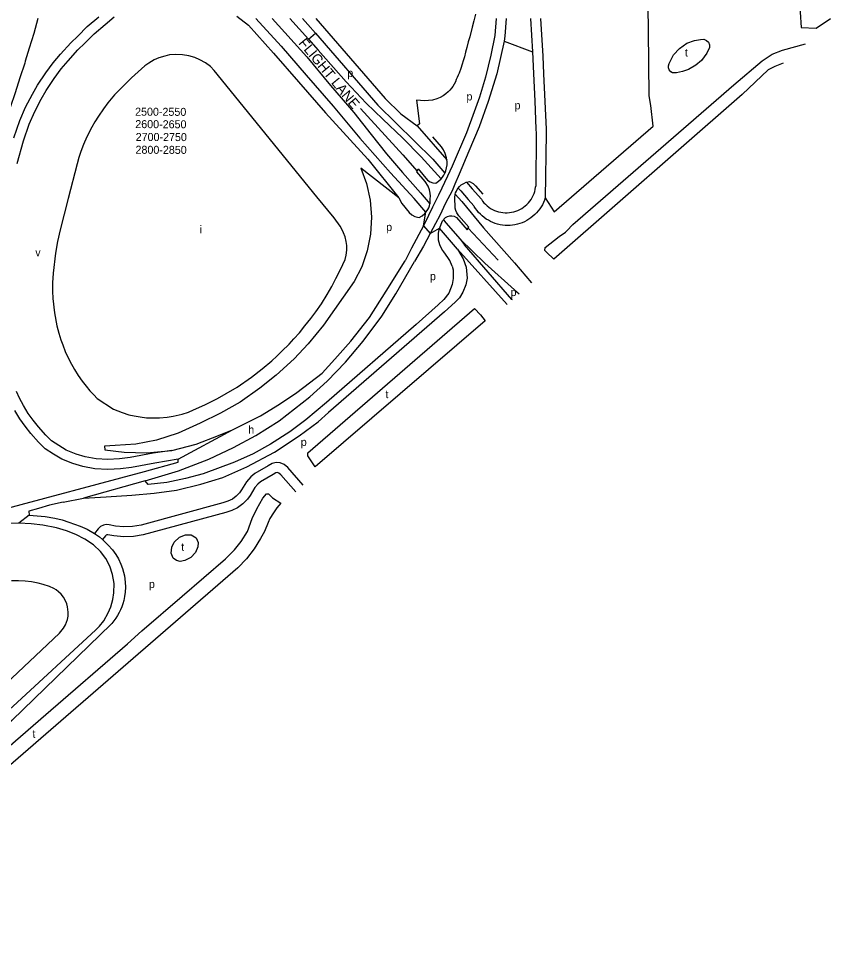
# Model space of a CAD drawing. Extents: x 154765 to 156627, y 383996 to 386132.
# Drawn here: x 155986.3 to 156392.2, y 384040.6 to 384500 of the extents above; entities that cross this region are included whole.
import ezdxf

# ---------------------------------------------------------------- set-up
doc = ezdxf.new("R2010")
doc.units = 0
for name, color, linetype in [('BLT_Basislijn', 7, 'Continuous'), ('BLT_Bebouwing', 7, 'Continuous'), ('BLT_Centroide', 7, 'Continuous'), ('BLT_Huisnummer_reeks', 7, 'Continuous'), ('BLT_Straatnaam', 7, 'Continuous'), ('BLT_Vlakafsluiter', 7, 'Continuous')]:
    doc.layers.add(name, color=color, linetype=linetype)

msp = doc.modelspace()

# ---------------------------------------------------------------- linework, layer by layer
at = {"layer": 'BLT_Basislijn'}
for p, q in [((156095.52, 384501.07), (156101.2, 384496.63)), ((156121.91, 384499.98), (156131.18, 384489.58)), ((156128.33, 384499.98), (156130.93, 384496.97)), ((156130.93, 384496.97), (156134.7, 384492.61)), ((156134.93, 384499.98), (156169.64, 384459.92)), ((156131.18, 384489.58), (156134.7, 384492.61)), ((156134.7, 384492.61), (156165.86, 384456.65)), ((156224.31, 384491.47), (156222.3, 384481.68)), ((156131.18, 384489.58), (156136.02, 384484.16)), ((156229.05, 384488.58), (156225.43, 384472.27)), ((156113.81, 384482.67), (156126.3, 384468.25)), ((156117.52, 384486.02), (156130.06, 384471.54)), ((156136.02, 384484.16), (156150.01, 384468.24)), ((156130.41, 384480.75), (156142.29, 384466.38)), ((156222.3, 384481.68), (156219.64, 384470.58)), ((156130.06, 384471.54), (156143.57, 384456.1)), ((156219.64, 384470.58), (156216.75, 384460.69)), ((156225.43, 384472.27), (156221.09, 384458.51)), ((156126.3, 384468.25), (156139.8, 384452.81)), ((156142.29, 384466.38), (156153.87, 384452.87)), ((156150.01, 384468.24), (156160.14, 384457.62)), ((156169.64, 384459.92), (156177.39, 384452.32)), ((156216.75, 384460.69), (156214.1, 384453.21)), ((156143.57, 384456.1), (156156.83, 384440.18)), ((156157.24, 384454.87), (156178.47, 384431.71)), ((156160.14, 384457.62), (156168.34, 384449.66)), ((156165.86, 384456.65), (156193.33, 384429.69)), ((156221.09, 384458.51), (156216.51, 384445.73)), ((156160.83, 384429.64), (156139.8, 384452.81)), ((156153.87, 384452.87), (156162.55, 384442.01)), ((156177.39, 384452.32), (156185.64, 384446.31)), ((156214.1, 384453.21), (156210.24, 384442.83)), ((156168.34, 384449.66), (156178.23, 384440.25)), ((156185.64, 384446.31), (156200.38, 384429.29)), ((156216.51, 384445.73), (156211.44, 384433.66)), ((156162.55, 384442.01), (156170.27, 384432.36)), ((156210.24, 384442.83), (156203.12, 384426.13)), ((156245.03, 384442.47), (156244.84, 384416.16)), ((156250.02, 384442.65), (156249.56, 384410.32)), ((156156.83, 384440.18), (156172.2, 384422.77)), ((156178.23, 384440.25), (156187.64, 384430.84)), ((156170.27, 384432.36), (156178.23, 384422.95)), ((156211.44, 384433.66), (156206.56, 384422.21)), ((156160.83, 384429.64), (156176.43, 384410.23)), ((156178.47, 384431.71), (156185.51, 384423.71)), ((156187.64, 384430.84), (156197.61, 384419.87)), ((156193.33, 384429.69), (156199.47, 384422.71)), ((156176.43, 384410.23), (156157.43, 384425.11)), ((156184.02, 384409.92), (156172.2, 384422.77)), ((156178.23, 384422.95), (156187.15, 384412.81)), ((156203.12, 384426.13), (156200.8, 384421.19)), ((156199.3, 384418), (156197.93, 384415.08)), ((156200.8, 384421.19), (156199.3, 384418)), ((156206.56, 384422.21), (156204.38, 384417.11)), ((156210.19, 384418.07), (156213.07, 384414.79)), ((156197.93, 384415.08), (156196.2, 384411.57)), ((156203, 384413.87), (156199.8, 384407.59)), ((156204.38, 384417.11), (156203, 384413.87)), ((156206.09, 384415.17), (156207.35, 384413.73)), ((156207.35, 384413.73), (156211.07, 384409.49)), ((156213.07, 384414.79), (156217.64, 384409.59)), ((156176.43, 384410.23), (156177.82, 384407.45)), ((156189.89, 384403.09), (156184.02, 384409.92)), ((156187.15, 384412.81), (156191.92, 384407.23)), ((156196.2, 384411.57), (156193.28, 384405.64)), ((156204.6, 384412.08), (156207.9, 384408.4)), ((156211.07, 384409.49), (156213.88, 384406.29)), ((156193.28, 384405.64), (156191.24, 384401.51)), ((156199.8, 384407.59), (156196.81, 384401.51)), ((156207.9, 384408.4), (156218.75, 384395.37)), ((156191.24, 384401.51), (156188.66, 384396.28)), ((156196.81, 384401.51), (156194.72, 384397.47)), ((156188.66, 384396.28), (156182.74, 384385.16)), ((156194.72, 384397.47), (156192.06, 384392.4)), ((156205.73, 384384.65), (156196.77, 384395.08)), ((156198.68, 384399.33), (156199.94, 384397.85)), ((156199.94, 384397.85), (156207.1, 384389.69)), ((156211.04, 384395.18), (156225.99, 384379.1)), ((156218.75, 384395.37), (156234.19, 384377.75)), ((156192.06, 384392.4), (156188.77, 384386.13)), ((156188.77, 384386.13), (156184.19, 384378.41)), ((156207.1, 384389.69), (156209.28, 384386.75)), ((156182.74, 384385.16), (156179.6, 384378.89)), ((156205.73, 384384.65), (156208.62, 384379.83)), ((156205.73, 384384.65), (156230.47, 384356.94)), ((156170.14, 384363.63), (156179.6, 384378.89)), ((156174.94, 384362.37), (156184.19, 384378.41)), ((156234.19, 384377.75), (156242.69, 384367.77)), ((156203.07, 384376.23), (156203.55, 384374.28)), ((156203.55, 384374.28), (156203.55, 384369.93)), ((156203.55, 384369.93), (156203.07, 384367.04)), ((156210.55, 384370.18), (156209.83, 384366.8)), ((156161.8, 384350.48), (156170.14, 384363.63)), ((156203.07, 384367.04), (156201.38, 384362.7)), ((156208.38, 384363.18), (156206.69, 384360.28)), ((156209.83, 384366.8), (156208.38, 384363.18)), ((156167.86, 384351.24), (156174.94, 384362.37)), ((156198.97, 384359.56), (156196.08, 384356.91)), ((156201.38, 384362.7), (156198.97, 384359.56)), ((156206.69, 384360.28), (156204.52, 384358.11)), ((156196.08, 384356.91), (156185.07, 384347.08)), ((156204.52, 384358.11), (156199.21, 384353.29)), ((156199.21, 384353.29), (156141.2, 384302.96)), ((156152.45, 384338.6), (156161.8, 384350.48)), ((156158.51, 384338.6), (156167.86, 384351.24)), ((156185.07, 384347.08), (156140.18, 384308.01)), ((156144.36, 384329.75), (156152.45, 384338.6)), ((156149.67, 384328.24), (156158.51, 384338.6)), ((156138.04, 384322.67), (156144.36, 384329.75)), ((156140.57, 384318.63), (156149.67, 384328.24)), ((156125.4, 384313.07), (156138.04, 384322.67)), ((156131.97, 384310.79), (156140.57, 384318.63)), ((156116.81, 384307.25), (156125.4, 384313.07)), ((156116.56, 384298.91), (156131.97, 384310.79)), ((156140.18, 384308.01), (156129.95, 384299.39)), ((156107.35, 384301.4), (156116.81, 384307.25)), ((156093.35, 384294.4), (156107.35, 384301.4)), ((156104.93, 384291.57), (156116.56, 384298.91)), ((156129.95, 384299.39), (156121.86, 384293.32)), ((156136.02, 384298.37), (156141.2, 384302.96)), ((156086.23, 384291.57), (156093.35, 384294.4)), ((156126.67, 384291.29), (156136.02, 384298.37)), ((156066.09, 384292.71), (156055.35, 384289.23)), ((156075.11, 384287.28), (156086.23, 384291.57)), ((156093.81, 384285.51), (156104.93, 384291.57)), ((156121.86, 384293.32), (156112.26, 384287.25)), ((156114.28, 384283.2), (156126.67, 384291.29)), ((156034.61, 384286.57), (156029.34, 384286.27)), ((156029.34, 384286.27), (156029.45, 384284.29)), ((156044.93, 384287.16), (156034.61, 384286.57)), ((156055.35, 384289.23), (156044.93, 384287.16)), ((156062.98, 384283.99), (156075.11, 384287.28)), ((156081.43, 384279.69), (156093.81, 384285.51)), ((156112.26, 384287.25), (156103.67, 384282.45)), ((156029.45, 384284.29), (156039.1, 384283.18)), ((156039.1, 384283.18), (156050.53, 384282.89)), ((156050.53, 384282.89), (156062.98, 384283.99)), ((156103.67, 384282.45), (156094.32, 384278.15)), ((156100.38, 384275.87), (156114.28, 384283.2)), ((156049.38, 384273.6), (156066.06, 384278.15)), ((156066.06, 384278.15), (156066.06, 384279.67)), ((156066.26, 384273.88), (156081.43, 384279.69)), ((156094.32, 384278.15), (156078.65, 384272.33)), ((156088.5, 384270.56), (156100.38, 384275.87)), ((155968.5, 384251.86), (156049.38, 384273.6)), ((156049.58, 384268.82), (156066.26, 384273.88)), ((156078.65, 384272.33), (156069.8, 384270.06)), ((156051.1, 384267.02), (156049.58, 384268.82)), ((156060.45, 384268.03), (156051.1, 384267.02)), ((156069.8, 384270.06), (156060.45, 384268.03)), ((156065.25, 384264.24), (156077.38, 384267.27)), ((156077.38, 384267.27), (156088.5, 384270.56)), ((156043.01, 384261.71), (156054.13, 384262.72)), ((156054.13, 384262.72), (156065.25, 384264.24)), ((156008.64, 384258.17), (156018.75, 384260.2)), ((156018.75, 384260.2), (156030.12, 384260.95)), ((156030.12, 384260.95), (156043.01, 384261.71)), ((155996.38, 384255.07), (155991.55, 384253.7)), ((155991.55, 384253.7), (155991.75, 384251.75))]:
    msp.add_line(p, q, dxfattribs=at)
for points in [[(156249.56, 384410.32), (156254.04, 384403.35), (156303.52, 384446.2), (156302.33, 384456.38), (156301.55, 384461.23), (156301.14, 384493.68), (156300.55, 384542.72)], [(156375.01, 384533.94), (156377.47, 384495.36), (156384.99, 384495.16), (156392.18, 384500)], [(155984.03, 384440.25), (155987.05, 384449.02), (155989.92, 384455.55), (155993.29, 384462.04), (155995.89, 384466.63), (155999.99, 384472.77), (156003.71, 384477.82), (156007.39, 384482.1), (156012.44, 384487.71), (156015.92, 384491.15), (156020.72, 384495.99), (156026.44, 384500.79)], [(155985.69, 384427.5), (155988.81, 384438.77), (155991.71, 384447.2), (155994.44, 384453.39), (155997.69, 384459.65), (156000.15, 384464.01), (156004.08, 384469.9), (156007.62, 384474.7), (156011.15, 384478.8), (156016.06, 384484.26), (156019.45, 384487.61), (156024.11, 384492.31), (156029.66, 384496.97), (156034.2, 384500.8)], [(156214.7, 384502.11), (156213.86, 384498.76), (156213.08, 384495.65), (156211.85, 384490.76), (156211.13, 384488.32), (156210.44, 384485.47), (156209.77, 384483.05), (156209.2, 384480.8), (156208.56, 384478.71), (156208.13, 384477.17), (156207.34, 384474.86), (156206.52, 384472.66), (156206.07, 384471.59), (156205.61, 384470.45), (156205.1, 384469.42), (156204.65, 384468.31), (156204.03, 384467.14), (156203.34, 384465.94), (156202.68, 384465.05), (156201.94, 384464.18), (156201.11, 384463.29), (156199.94, 384462.27), (156198.52, 384461.25), (156197.11, 384460.44), (156195.47, 384459.75), (156193.19, 384459.08), (156189.31, 384458.75), (156185.15, 384459.16), (156186.72, 384447.24), (156185.64, 384446.31)], [(155996.07, 384499.98), (155993.94, 384492.5), (155991.73, 384485.04), (155989.75, 384478.59)], [(156101.2, 384496.63), (156113.81, 384482.67)], [(156104.9, 384499.98), (156117.52, 384486.02)], [(156113.06, 384499.98), (156130.41, 384480.75)], [(156225.08, 384499.98), (156224.31, 384491.47)], [(156230.09, 384499.98), (156229.3, 384491.13), (156229.05, 384488.58)], [(156242.26, 384499.98), (156243.2, 384483.29)], [(156247.27, 384499.98), (156248.31, 384481.14)], [(156368.46, 384477.53), (156364.37, 384476.01), (156360.94, 384474.29), (156348, 384461.98), (156253.84, 384379.59), (156250.15, 384383.08), (156249.43, 384383.99), (156249.54, 384385.49), (156256.56, 384390.96), (156259.66, 384393.22), (156260.37, 384393.88), (156263.3, 384397.01), (156343.74, 384466.77), (156357.96, 384478.8), (156362.97, 384482.13), (156368.12, 384484.1), (156379.68, 384487.27)], [(156243.2, 384483.29), (156243.76, 384472.37), (156244.39, 384458.55), (156244.94, 384444.74), (156245.03, 384442.47)], [(155989.75, 384478.59), (155989.44, 384477.6), (155987.08, 384470.19), (155984.64, 384462.8), (155982.12, 384455.43), (155979.53, 384448.1), (155976.87, 384440.79), (155974.13, 384433.51), (155971.31, 384426.25), (155968.42, 384419.03), (155965.46, 384411.84), (155962.42, 384404.67), (155959.31, 384397.54), (155956.12, 384390.44), (155952.86, 384383.37), (155949.53, 384376.34), (155946.13, 384369.34), (155942.66, 384362.38), (155939.11, 384355.46), (155938.74, 384354.75)], [(156248.31, 384481.14), (156248.77, 384472.34), (156249.4, 384458.51), (156249.95, 384444.68), (156250.02, 384442.65)], [(156200.38, 384429.29), (156200.24, 384430.24), (156199.63, 384432.42), (156198.73, 384434.27), (156197.73, 384435.79), (156193.4, 384440.74)], [(156199.47, 384422.71), (156199.49, 384422.75), (156199.88, 384423.74), (156200.28, 384425.23), (156200.49, 384426.77), (156200.5, 384428.42), (156200.38, 384429.29)], [(156157.43, 384425.11), (156160.29, 384417.42), (156162.12, 384409.22), (156162.81, 384400.72), (156162.31, 384392.17), (156160.63, 384383.81), (156157.86, 384375.87), (156154.13, 384368.56)], [(156191.92, 384407.23), (156191.98, 384407.45), (156192.13, 384409.77), (156192.22, 384411.19), (156192.09, 384412.67), (156191.73, 384414.35), (156191.05, 384416.16), (156189.56, 384418.51), (156185.34, 384423.38), (156185.51, 384423.71)], [(156185.51, 384423.71), (156186.07, 384424.75), (156190.79, 384419.14), (156192, 384418.33), (156193.37, 384417.82), (156194.84, 384417.67), (156196.29, 384418.59), (156197.58, 384419.83), (156197.61, 384419.87)], [(156197.61, 384419.87), (156198.19, 384420.58), (156198.95, 384421.68), (156199.47, 384422.71)], [(156206.09, 384415.17), (156206.7, 384415.89), (156207.62, 384416.73), (156208.81, 384417.5), (156210.1, 384418.05), (156210.19, 384418.07)], [(156210.19, 384418.07), (156211.69, 384418.43), (156213.48, 384417.39), (156214.72, 384416.29), (156218.32, 384412.12)], [(156204.6, 384412.08), (156204.8, 384412.79), (156205.14, 384413.64), (156205.55, 384414.4), (156206.06, 384415.15), (156206.09, 384415.17)], [(156217.64, 384409.59), (156218.26, 384408.7), (156218.95, 384407.86), (156219.7, 384407.07), (156220.51, 384406.33), (156221.37, 384405.66), (156222.27, 384405.05), (156223.22, 384404.52), (156224.2, 384404.05), (156225.21, 384403.65), (156226.26, 384403.33), (156227.32, 384403.09), (156228.39, 384402.93), (156229.48, 384402.84), (156230.57, 384402.84), (156231.66, 384402.92), (156232.73, 384403.07), (156233.8, 384403.3), (156234.84, 384403.62), (156235.86, 384404), (156236.85, 384404.46), (156237.8, 384405), (156238.71, 384405.6), (156239.57, 384406.26), (156240.38, 384406.99), (156241.13, 384407.77), (156241.83, 384408.61), (156242.46, 384409.5), (156243.03, 384410.43), (156243.52, 384411.4), (156243.95, 384412.4), (156244.3, 384413.43), (156244.57, 384414.49), (156244.76, 384415.56), (156244.84, 384416.16)], [(156211.04, 384395.18), (156211.3, 384395.62), (156206.32, 384401.33), (156205.37, 384402.89), (156204.91, 384403.99), (156204.56, 384405.16), (156204.49, 384406.57), (156204.38, 384409.06), (156204.36, 384410.67), (156204.53, 384411.84), (156204.6, 384412.08)], [(156249.56, 384410.32), (156249.15, 384409.13), (156248.67, 384407.98), (156248.12, 384406.86), (156247.49, 384405.77), (156246.8, 384404.73), (156246.04, 384403.73), (156245.22, 384402.79), (156244.34, 384401.9), (156243.41, 384401.06), (156242.42, 384400.29), (156241.39, 384399.58), (156240.32, 384398.94), (156239.2, 384398.37), (156238.05, 384397.88), (156236.87, 384397.45), (156235.67, 384397.11), (156234.45, 384396.84), (156233.21, 384396.64), (156231.97, 384396.53), (156230.71, 384396.5), (156229.46, 384396.55), (156228.22, 384396.68), (156226.99, 384396.88), (156225.77, 384397.17), (156224.57, 384397.53), (156223.4, 384397.97), (156222.25, 384398.48), (156221.15, 384399.07), (156220.08, 384399.72), (156219.06, 384400.44), (156218.08, 384401.23), (156217.16, 384402.07), (156216.29, 384402.97), (156215.48, 384403.93), (156214.74, 384404.94), (156214.06, 384405.99), (156213.88, 384406.29)], [(156177.82, 384407.45), (156181.64, 384403.04), (156182.93, 384401.77), (156184.43, 384400.93), (156185.8, 384400.58), (156186.5, 384400.53), (156188, 384401.34), (156189.39, 384402.53), (156189.89, 384403.09)], [(156189.89, 384403.09), (156190.02, 384403.23), (156190.9, 384404.44), (156191.34, 384405.38), (156191.7, 384406.35), (156191.92, 384407.23)], [(156198.68, 384399.33), (156198.84, 384399.58), (156199.75, 384400.45), (156200.65, 384400.96), (156201.92, 384401.32), (156202.96, 384401.32), (156204.13, 384401.08), (156205.26, 384400.49), (156210.57, 384394.36), (156211.04, 384395.18)], [(156203.07, 384376.23), (156201.83, 384379.02), (156200.91, 384380.52), (156198.84, 384383.24), (156197.86, 384384.69), (156196.85, 384386.82), (156196.23, 384389.08), (156196.16, 384391.15), (156196.28, 384392.72), (156196.57, 384394.33), (156196.77, 384395.08)], [(156196.77, 384395.08), (156196.84, 384395.35), (156197.53, 384397.22), (156198.29, 384398.73), (156198.68, 384399.33)], [(156207.1, 384389.69), (156219.42, 384377.68), (156234.26, 384364.4), (156236.53, 384362.3)], [(156233.15, 384359.31), (156232.94, 384359.53), (156209.28, 384386.75)], [(156208.62, 384379.83), (156210.07, 384375.73), (156210.55, 384370.18)], [(156154.13, 384368.56), (156138.7, 384346.73), (156131.15, 384337.36), (156124.04, 384329.78)], [(156124.04, 384329.78), (156115.13, 384321.61), (156106.9, 384315.22), (156097.03, 384308.24), (156087.31, 384302.77), (156077.04, 384297.77), (156066.09, 384292.71)], [(156062.98, 384283.99), (156053.59, 384282.64), (156042.12, 384280.49), (156036.79, 384279.83), (156031.04, 384279.5), (156025.15, 384279.85), (156019.63, 384280.87), (156015.17, 384282.22), (156010.23, 384284.24), (156006.52, 384286.46), (156002.83, 384288.83), (155999.98, 384291.67), (155996.32, 384295.81), (155993.64, 384299.17), (155991.22, 384302.58), (155988.81, 384306.48), (155986.88, 384310.24), (155985.26, 384313.52)], [(156066.06, 384279.67), (156054.46, 384277.72), (156042.89, 384275.54), (156037.24, 384274.84), (156031.03, 384274.49), (156024.54, 384274.88), (156018.44, 384276), (156013.49, 384277.51), (156007.99, 384279.75), (156003.88, 384282.21), (155999.68, 384284.91), (155996.34, 384288.24), (155992.49, 384292.59), (155989.64, 384296.17), (155987.05, 384299.82), (155984.45, 384304.02)], [(156128.62, 384266.68), (156120.99, 384275.46), (156119.14, 384277.1), (156117.15, 384277.87), (156115.08, 384278), (156113.12, 384277.53), (156111.06, 384276.39), (156104.5, 384272.48), (156102.38, 384270.81), (156100.35, 384268.44), (156097.84, 384264.31), (156096.86, 384262.91), (156095.18, 384261.17), (156093.22, 384259.77), (156091.01, 384258.69), (156088.53, 384257.89), (156047.57, 384246.8), (156043.3, 384246.05), (156039.05, 384245.85), (156034.76, 384246.29), (156031.57, 384246.9), (156030.11, 384247), (156028.76, 384246.64), (156027.38, 384245.98), (156026.18, 384244.9), (156024.29, 384242.57)], [(156124.88, 384263.36), (156117.43, 384271.93), (156116.5, 384272.76), (156116.05, 384272.93), (156115.52, 384272.97), (156114.95, 384272.83), (156113.55, 384272.05), (156107.34, 384268.35), (156105.86, 384267.18), (156104.41, 384265.49), (156102.03, 384261.57), (156100.74, 384259.72), (156098.46, 384257.37), (156095.79, 384255.45), (156092.88, 384254.04), (156089.95, 384253.09), (156048.65, 384241.92), (156043.85, 384241.07), (156038.91, 384240.84), (156034.04, 384241.34), (156030.92, 384241.93), (156030.59, 384241.95), (156030.5, 384241.93), (156030.19, 384241.78), (156029.81, 384241.44), (156028.29, 384239.56)], [(155876.92, 384045.31), (156000, 384152.12), (156040.86, 384187.42), (156047.93, 384193.86), (156068.05, 384211.2), (156089.71, 384229.87), (156094.33, 384234.42), (156097.6, 384238.52), (156100.73, 384243.59), (156103.15, 384250), (156105.47, 384254.95), (156108.47, 384260.26), (156110.24, 384262.4), (156111.26, 384262.43), (156111.8, 384261.86), (156113.26, 384260.31), (156117.39, 384257.71), (156115.48, 384255.37), (156113.74, 384252.9), (156112.02, 384250), (156111.18, 384248.08), (156109.19, 384243.53), (156107.28, 384240.01), (156104.05, 384234.87), (156100.23, 384229.89), (156095.98, 384225.36), (156000, 384142.36), (155882.67, 384040.61)], [(156008.64, 384258.17), (156001.76, 384256.65), (155996.38, 384255.07)], [(155991.75, 384251.75), (155999.69, 384251.03), (156004.51, 384250.27), (156008.15, 384249.37), (156011.55, 384248.3), (156017.1, 384246.21), (156020.67, 384244.66), (156024.29, 384242.57)], [(155986.43, 384247.71), (155980.1, 384247.52), (155972.23, 384246.35)], [(156033.49, 384209.53), (156034.03, 384212.97), (156034.09, 384217.61), (156033.38, 384222.05), (156031.97, 384226.26), (156029.95, 384230.11), (156027.32, 384233.54), (156023.76, 384236.91), (156019.41, 384239.78), (156014.99, 384242.08), (156010.36, 384243.96), (156005.39, 384245.44), (155998.53, 384246.76), (155992.69, 384247.46), (155986.43, 384247.71)], [(156024.29, 384242.57), (156024.3, 384242.56), (156026.74, 384240.84), (156028.29, 384239.56)], [(156028.29, 384239.56), (156028.82, 384239.12), (156031.22, 384236.77), (156033.26, 384234.42), (156034.94, 384232.09), (156036.26, 384229.86), (156037.54, 384227.2), (156038.31, 384225.07), (156039.25, 384221.36), (156039.67, 384218.31), (156039.75, 384215.68), (156039.7, 384213.25), (156039.37, 384211.09), (156039.04, 384209), (156038.54, 384207.46), (156037.97, 384205.94), (156037.32, 384204.46), (156036.6, 384203.01), (156035.81, 384201.6), (156034.95, 384200.22), (156034.02, 384198.89), (156033.03, 384197.61), (156032.7, 384197.21)], [(156025.06, 384194.36), (156026.86, 384196.28), (156028.98, 384198.99), (156031.19, 384202.87), (156032.49, 384205.91), (156033.49, 384209.53)], [(156025.06, 384194.36), (155983.47, 384156.08), (155923.24, 384102.87)], [(156032.7, 384197.21), (155982.99, 384149.03), (155929.31, 384102.14)]]:
    msp.add_lwpolyline(points, dxfattribs=at)
for points in [[(156311.49, 384477.4), (156313.68, 384481.77), (156316.64, 384484.91), (156320.28, 384487.61), (156324.1, 384488.96), (156327.14, 384489.46), (156328.76, 384489.53), (156330.21, 384488.96), (156331.18, 384488.05), (156331.66, 384486.83), (156331.67, 384485.51), (156330.24, 384482.53), (156327.59, 384478.96), (156324.77, 384476.6), (156321.2, 384474.49), (156318.22, 384473.36), (156315.22, 384472.8), (156313.23, 384472.83), (156312.32, 384473.32), (156311.54, 384474.22), (156311.12, 384475.31), (156311.13, 384476.32)], [(156214.29, 384355.03), (156217.15, 384351.9), (156219.62, 384348.85), (156134.61, 384275.95), (156130.9, 384281.41), (156130.9, 384282.8)], [(156062.71, 384232.76), (156063.01, 384235.75), (156064.14, 384238.27), (156066.86, 384240.66), (156069.82, 384241.82), (156072.6, 384241.81), (156075.08, 384240.46), (156076.16, 384238.14), (156075.93, 384235.91), (156074.82, 384233.06), (156072.54, 384230.59), (156069.41, 384229.01), (156067.14, 384228.54), (156065.24, 384229), (156063.63, 384230.28)]]:
    msp.add_lwpolyline(points, close=True, dxfattribs=at)
at = {"layer": 'BLT_Bebouwing'}
for points in [[(156150.44, 384384.2), (156150.42, 384384.88), (156150.39, 384386.49), (156150.11, 384388.54), (156149.53, 384390.88), (156148.82, 384392.88), (156147.77, 384394.93), (156147.01, 384396.12), (156144.1, 384400.36), (156135.5, 384410.86), (156084.05, 384473.96), (156082.21, 384475.92), (156079.73, 384477.73), (156076.92, 384479.35), (156074.49, 384480.4), (156071.49, 384481.26), (156068.35, 384481.78), (156064.96, 384481.93), (156061.82, 384481.69), (156059.49, 384481.16), (156056.49, 384480.26), (156054.2, 384479.26), (156051.53, 384477.64), (156049.5, 384476.34), (156042.84, 384470.25), (156034.38, 384461.75), (156030.99, 384457.74), (156028.8, 384454.74), (156026.27, 384451.12), (156024.56, 384448.26), (156022.98, 384445.59), (156020.52, 384440.76), (156018.85, 384436.89), (156017.57, 384433.46), (156016.47, 384430.41), (156015.59, 384427.24), (156011.14, 384409.91), (156007.1, 384394.39), (156005.76, 384388.53), (156004.76, 384382.72), (156003.62, 384372.73), (156003.34, 384367.76), (156003.29, 384363.61), (156003.57, 384359.99), (156004.34, 384352.77), (156005.52, 384346.29), (156006.47, 384342.62), (156007.47, 384339.38), (156008.47, 384336.76), (156009.72, 384333.54), (156011.99, 384328.73), (156014.37, 384324.5), (156016.23, 384321.55), (156018.23, 384318.74), (156020.23, 384316.21), (156022.04, 384313.87), (156023.99, 384311.78), (156025.62, 384310.07), (156033.88, 384304.75), (156038.07, 384303.08), (156041.5, 384301.89), (156044.12, 384301.36), (156047.22, 384300.79), (156050.31, 384300.41), (156053.81, 384300.39), (156056.72, 384300.41), (156060.63, 384300.69), (156063.63, 384301.26), (156068.1, 384302.26)], [(156068.1, 384302.26), (156071.25, 384303.27), (156073.82, 384304.36), (156079.52, 384306.83), (156085.71, 384310.02), (156090.19, 384312.45), (156095.57, 384315.74), (156102.7, 384320.67), (156108.03, 384324.87), (156112.89, 384328.87), (156115.46, 384331.26), (156117.96, 384333.62), (156121.55, 384337.18), (156123.98, 384339.85), (156126.69, 384342.9), (156129.45, 384346.29), (156132.45, 384349.96), (156134.88, 384353.39), (156137.69, 384357.41), (156140.55, 384361.94), (156142.88, 384365.99), (156144.98, 384369.95), (156146.79, 384373.52), (156148.43, 384376.95), (156149.58, 384379.53), (156150.06, 384381.63), (156150.44, 384384.2), (156150.44, 384384.2)], [(155976.77, 384164.62), (156006.85, 384192.8), (156008.89, 384195.23), (156009.86, 384196.96), (156010.38, 384198.24), (156010.82, 384199.61), (156011.14, 384201.3), (156011.18, 384203.24), (156010.86, 384205.84), (156010.47, 384207.39), (156009.68, 384209.19), (156008.77, 384210.75), (156007.65, 384212.19), (156006.39, 384213.45), (156005.18, 384214.39), (156004.05, 384215.13), (156001.87, 384216.1), (155998.7, 384217.15), (155996.14, 384217.79), (155992.82, 384218.4), (155989.59, 384218.77), (155986.33, 384218.98), (155982.79, 384218.98)]]:
    msp.add_lwpolyline(points, dxfattribs=at)
at = {"layer": 'BLT_Vlakafsluiter'}
for p, q in [((156229.05, 384488.58), (156243.2, 384483.29)), ((156188.66, 384396.28), (156189.89, 384403.09)), ((156188.66, 384396.28), (156192.06, 384392.4)), ((156192.06, 384392.4), (156196.77, 384395.08)), ((156066.06, 384279.67), (156093.35, 384294.4)), ((156049.58, 384268.82), (156018.75, 384260.2)), ((155991.75, 384251.75), (155986.43, 384247.71))]:
    msp.add_line(p, q, dxfattribs=at)

# ---------------------------------------------------------------- texts
at = {"layer": 'BLT_Centroide'}
for s, p in [('t', (156319.37, 384480.93)), ('p', (156150.67, 384470.71)), ('p', (156210.19, 384458.96)), ('p', (156234.21, 384454.57)), ('i', (156076.86, 384392.53)), ('p', (156170.06, 384393.72)), ('v', (155994.73, 384381.06)), ('p', (156191.96, 384369.13)), ('p', (156232.22, 384361.2)), ('h', (156101.14, 384292.44)), ('p', (156127.4, 384286.29)), ('t', (156067.66, 384233.85)), ('p', (156051.52, 384215.29))]:
    msp.add_text(s, height=4, dxfattribs=at).set_placement(p)
for p in [(156169.74, 384310.19), (155993.32, 384140.44)]:
    msp.add_text('t', height=4, rotation=1, dxfattribs=at).set_placement(p)
at = {"layer": 'BLT_Huisnummer_reeks'}
for s, p in [('2500-2550', (156044.6, 384451.35)), ('2600-2650', (156044.69, 384445.14)), ('2700-2750', (156044.9, 384438.74)), ('2800-2850', (156044.81, 384432.34))]:
    msp.add_text(s, height=4, rotation=359.8053, dxfattribs=at).set_placement(p)
at = {"layer": 'BLT_Straatnaam'}
msp.add_text('FLIGHT LANE', height=5, rotation=309.5841, dxfattribs=at).set_placement((156125.98, 384487.48))

doc.saveas('drawing.dxf')
